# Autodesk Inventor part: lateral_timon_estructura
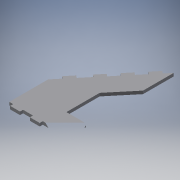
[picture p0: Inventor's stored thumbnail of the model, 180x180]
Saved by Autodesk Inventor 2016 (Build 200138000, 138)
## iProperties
Created: 2017-06
Part Number: lateral_timon_estructura
Material: Generic
Document SubType Name: Modeling
Designer: laboratorioesan
Density: 1 g/cm^3
Appearance: Default
Author: laboratorioesan
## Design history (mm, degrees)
sketch "Sketch1"
  geometry: L1 (0, 0)-(32.036, 38.389) reference; L2 (0, 0)-(11.901, -9.931) reference; L3 (43.937, 28.458)-(11.901, -9.931) reference; L4 (32.036, 38.389)-(43.937, 28.458) reference; L5 (-64.072, -76.777)-(-32.036, -38.389) reference; L6 (-64.072, -76.777)-(-52.172, -86.709) reference; L7 (-20.136, -48.32)-(-52.172, -86.709) reference; L8 (-32.036, -38.389)-(-20.136, -48.32) reference; L9 (-128.144, -153.555)-(-96.108, -115.166) reference; L10 (-128.144, -153.555)-(-116.244, -163.486) reference; L11 (-84.208, -125.097)-(-116.244, -163.486) reference; L12 (-96.108, -115.166)-(-84.208, -125.097) reference; L13 (-198.623, -238.01)-(-166.587, -199.621) reference; L14 (-198.623, -238.01)-(-186.723, -247.941) reference; L15 (-154.687, -209.552)-(-186.723, -247.941) reference; L16 (-166.587, -199.621)-(-154.687, -209.552) reference; L17 (-0.435, -485.534)-(49.565, -485.534) reference; L18 (-0.435, -485.534)-(-0.435, -501.034) reference; L19 (49.565, -501.034)-(-0.435, -501.034) reference; L20 (49.565, -485.534)-(49.565, -501.034) reference; L21 (-100.435, -485.534)-(-50.435, -485.534) reference; L22 (-100.435, -485.534)-(-100.435, -501.034) reference; L23 (-50.435, -501.034)-(-100.435, -501.034) reference; L24 (-50.435, -485.534)-(-50.435, -501.034) reference; L25 (-200.44, -485.534)-(-150.44, -485.534) reference; L26 (-200.44, -485.534)-(-200.44, -501.034) reference; L27 (-150.44, -501.034)-(-200.44, -501.034) reference; L28 (-150.44, -485.534)-(-150.44, -501.034) reference; L29 (-220.44, -485.534)-(69.565, -485.534); L30 (69.565, -485.534)-(69.565, 59.169); L31 (69.565, 59.169)-(-220.44, -288.345); L32 (-220.44, -288.345)-(-220.44, -485.534)
  constraints: 8 end point, 1 collinear, 1 horizontal, 1 parallel, 1 perpendicular, 1 point on line
  dimensions: "d0" = 20 distance of L25.start L29.start; "d1" = 20 distance of L29.end L17.end
extrude "Extrusion1" new body sketch "Sketch1" distance "d2" = 15.5; taper "d3" = 0 deg
sketch "Sketch2"
  geometry: L1 (-96.108, -115.166)-(-128.144, -153.555) reference; L2 (-128.144, -153.555)-(-116.244, -163.486) reference; L3 (-116.244, -163.486)-(-154.687, -209.552) reference; L4 (-154.687, -209.552)-(-166.587, -199.621) reference; L5 (-166.587, -199.621)-(-198.623, -238.01) reference; L6 (-198.623, -238.01)-(-186.723, -247.941) reference; L7 (-186.723, -247.941)-(-220.44, -288.345) reference; L8 (-220.44, -288.345)-(-220.44, -485.534) reference; L9 (-220.44, -485.534)-(69.565, -485.534) reference; L10 (69.565, -485.534)-(69.565, 59.169) reference; L11 (69.565, 59.169)-(43.937, 28.458) reference; L12 (43.937, 28.458)-(32.036, 38.389) reference; L13 (32.036, 38.389)-(0, 0) reference; L14 (0, 0)-(11.901, -9.931) reference; L15 (11.901, -9.931)-(-20.136, -48.32) reference; L16 (-20.136, -48.32)-(-32.036, -38.389) reference; L17 (-32.036, -38.389)-(-64.072, -76.777) reference; L18 (-64.072, -76.777)-(-52.172, -86.709) reference; L19 (-52.172, -86.709)-(-84.208, -125.097) reference; L20 (-84.208, -125.097)-(-96.108, -115.166) reference; L21 (69.565, -485.534)-(69.565, 59.169) reference; L22 (69.565, -96.906)-(-30.435, -216.736); L23 (-30.435, -216.736)-(-30.435, -385.534); L24 (-30.435, -385.534)-(69.565, -385.534); 1 further point
  constraints: 6 end point, 2 parallel, 2 point on line, 1 perpendicular
  dimensions: "d4" = 100 distance between parallel lines of L9 L24; "d5" = 100 distance between parallel lines of L19 L22; "d6" = 100 distance between parallel lines of L10 L23
extrude "Extrusion2" cut sketch "Sketch2" distance "d7" = 15.5; taper "d8" = 0 deg
sketch "Sketch3"
  geometry: L1 (-50.435, -485.534)-(-100.435, -485.534) reference; L2 (-50.435, -485.534)-(-50.435, -501.034) reference; L3 (-100.435, -501.034)-(-50.435, -501.034) reference; L4 (-100.435, -485.534)-(-100.435, -501.034) reference; L5 (49.565, -485.534)-(-0.435, -485.534) reference; L6 (49.565, -485.534)-(49.565, -501.034) reference; L7 (-0.435, -501.034)-(49.565, -501.034) reference; L8 (-0.435, -485.534)-(-0.435, -501.034) reference; L9 (-150.44, -485.534)-(-200.44, -485.534) reference; L10 (-150.44, -485.534)-(-150.44, -501.034) reference; L11 (-200.44, -501.034)-(-150.44, -501.034) reference; L12 (-200.44, -485.534)-(-200.44, -501.034) reference; 1 further point
extrude "Extrusion3" join sketch "Sketch3" distance "d9" = 15.5; taper "d10" = 0 deg
fillet "Fillet1" dims "d11" = 80
fillet "Fillet2" dims "d12" = 80
fillet "Fillet3" dims "d13" = 80
sketch "Sketch4"
  geometry: L1 (69.565, -67.91)-(69.565, 59.169) reference; L2 (69.565, 59.169)-(43.937, 28.458) reference; L3 (43.937, 28.458)-(32.036, 38.389) reference; L4 (32.036, 38.389)-(0, 0) reference; L5 (0, 0)-(11.901, -9.931) reference; L6 (11.901, -9.931)-(-20.136, -48.32) reference; L7 (-20.136, -48.32)-(-32.036, -38.389) reference; L8 (-32.036, -38.389)-(-64.072, -76.777) reference; L9 (-64.072, -76.777)-(-52.172, -86.709) reference; L10 (-52.172, -86.709)-(-84.208, -125.097) reference; L11 (-84.208, -125.097)-(-96.108, -115.166) reference; L12 (-96.108, -115.166)-(-128.144, -153.555) reference; L13 (-128.144, -153.555)-(-116.244, -163.486) reference; L14 (-116.244, -163.486)-(-154.687, -209.552) reference; L15 (-154.687, -209.552)-(-166.587, -199.621) reference; L16 (-166.587, -199.621)-(-198.623, -238.01) reference; L17 (-198.623, -238.01)-(-186.723, -247.941) reference; L18 (-186.723, -247.941)-(-220.44, -288.345) reference; L19 (-220.44, -288.345)-(-220.44, -485.534) reference; L20 (-220.44, -485.534)-(-200.44, -485.534) reference; L21 (-200.44, -485.534)-(-200.44, -501.034) reference; L22 (-200.44, -501.034)-(-150.44, -501.034) reference; L23 (-150.44, -501.034)-(-150.44, -485.534) reference; L24 (-150.44, -485.534)-(-100.435, -485.534) reference; L25 (-100.435, -485.534)-(-100.435, -501.034) reference; L26 (-100.435, -501.034)-(-50.435, -501.034) reference; L27 (-50.435, -501.034)-(-50.435, -485.534) reference; L28 (-50.435, -485.534)-(-0.435, -485.534) reference; L29 (-0.435, -485.534)-(-0.435, -501.034) reference; L30 (-0.435, -501.034)-(49.565, -501.034) reference; L31 (49.565, -501.034)-(49.565, -485.534) reference; L32 (49.565, -485.534)-(69.565, -485.534) reference; L33 (69.565, -485.534)-(69.565, -385.534) reference; L34 (69.565, -385.534)-(49.565, -385.534) reference; L35 (-30.435, -305.534)-(-30.435, -245.731) reference; L36 (-11.857, -194.474)-(50.987, -119.168) reference; L37 (69.565, 59.169)-(142.147, -9.931); L38 (142.147, -9.931)-(24.606, -150.781); A1 r 80 centre (-10.435, -67.91) between (50.987, -119.168) and (69.565, -67.91) reference; A2 r 80 centre (49.565, -305.534) between (-30.435, -305.534) and (49.565, -385.534) reference; A3 r 80 centre (49.565, -245.731) between (-11.857, -194.474) and (-30.435, -245.731) reference; 1 further point
  constraints: 4 end point, 1 point on line
extrude "Extrusion4" join sketch "Sketch4" distance "d14" = 15.5; taper "d15" = 0 deg
body "Solid1"
node "Reference1"
node "Reference2"
node "Reference3"
node "Reference4"
node "Reference5"
node "Reference6"
node "Reference7"
node "Reference8"
node "Projected Loop1"
node "Reference9"
node "Reference10"
node "Reference11"
node "Projected Loop2"
